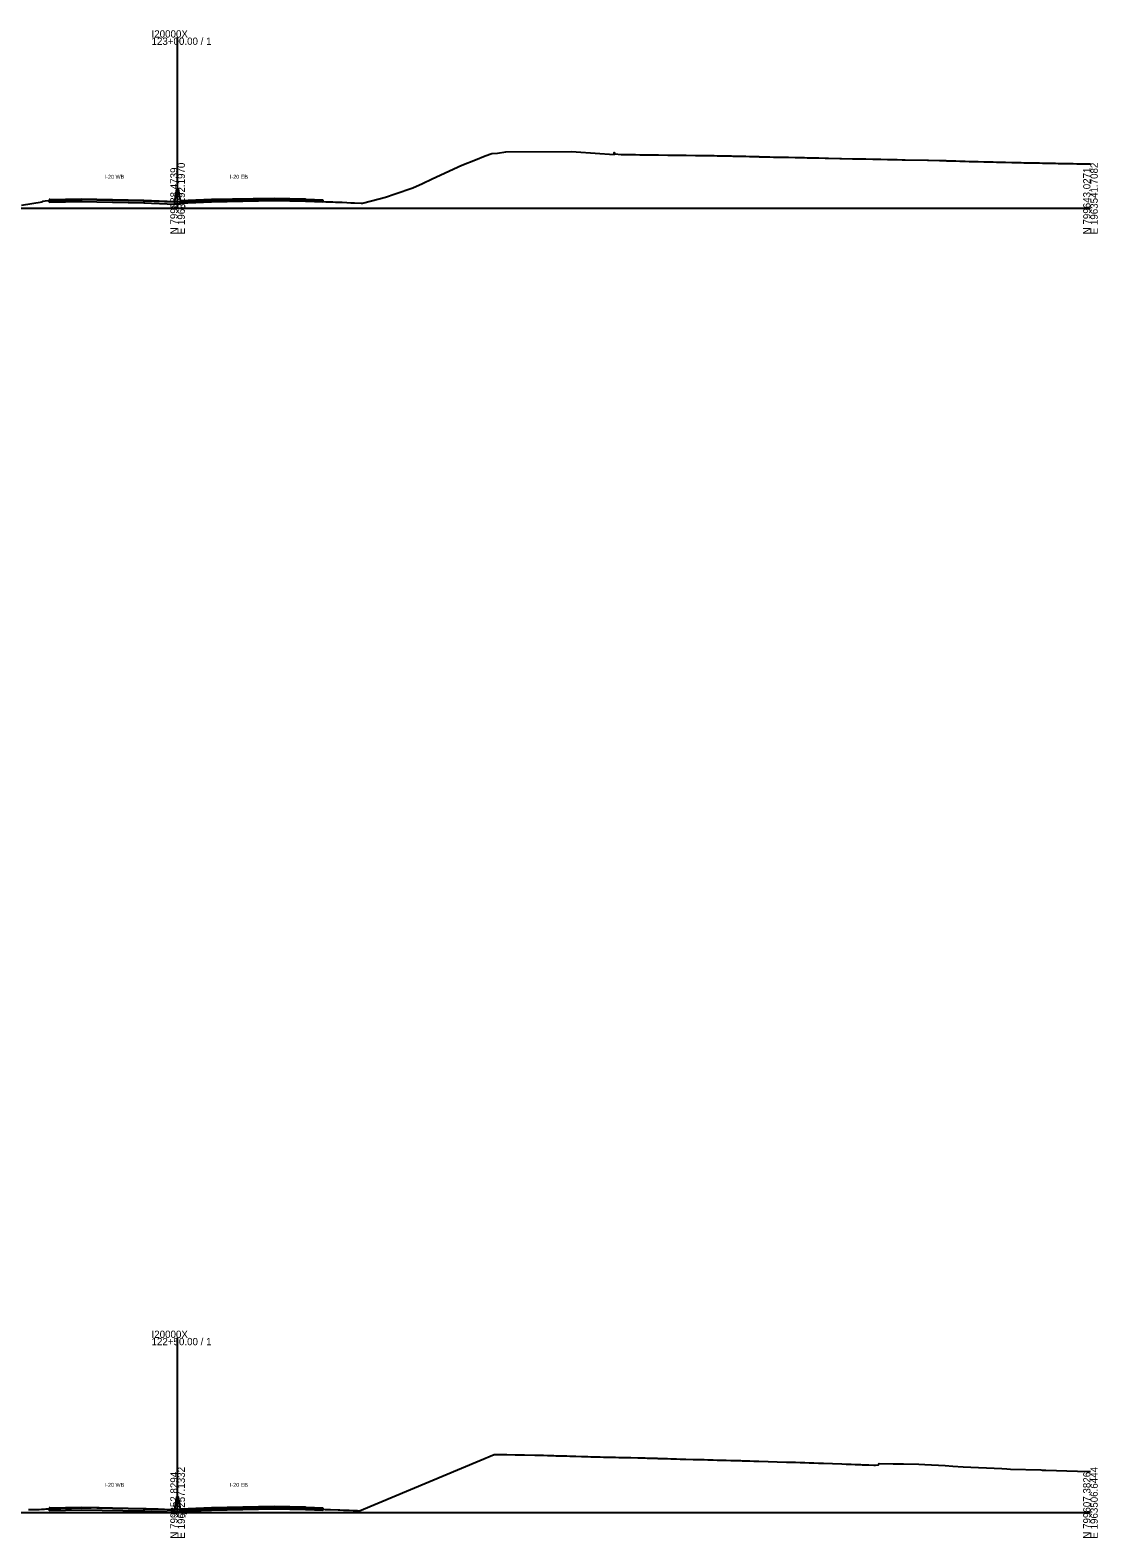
# Model space of a CAD drawing. Extents: x -4026 to 9638, y -10 to 19609.
# Drawn here: x 2293 to 2703, y 3990 to 4568 of the extents above; entities that cross this region are included whole.
import ezdxf

# ---------------------------------------------------------------- set-up
doc = ezdxf.new("R2010")
doc.units = 0
for name, color, linetype in [('RD_GPK_XS_Cell', 7, 'Continuous'), ('RD_TX_Misc1', 7, 'Continuous'), ('RD_XS_Base', 7, 'Continuous'), ('RD_XS_ExGround', 7, 'Continuous'), ('RD_XS_MedBWall', 7, 'Continuous'), ('RD_XS_Pave', 7, 'Continuous'), ('RD_XS_PaveOvlay', 7, 'Continuous'), ('RD_XS_TX_Elev_EX', 7, 'Continuous')]:
    doc.layers.add(name, color=color, linetype=linetype)

msp = doc.modelspace()

# ---------------------------------------------------------------- linework, layer by layer
at = {"layer": 'RD_GPK_XS_Cell'}
for p, q in [((2350, 4500), (2350, 4565.43)), ((2000, 4500), (2350, 4500)), ((2350, 4500), (2700, 4500)), ((2350, 4000), (2350, 4066.94)), ((2000, 4000), (2350, 4000)), ((2350, 4000), (2700, 4000))]:
    msp.add_line(p, q, dxfattribs=at)
at = {"layer": 'RD_XS_Base'}
for points in [[(2300.75, 4502.97), (2301, 4502.98)], [(2300.75, 4502.3), (2300.75, 4502.97)], [(2337, 4502.74), (2313, 4503.23), (2301, 4502.98)], [(2301, 4502.98), (2301, 4502.31)], [(2301, 4502.31), (2313, 4502.56), (2337, 4502.07)], [(2349, 4502.27), (2337, 4502.74)], [(2337, 4502.74), (2337, 4502.07)], [(2351, 4502.47), (2363, 4502.96)], [(2351, 4501.8), (2351, 4502.47)], [(2363, 4502.96), (2387, 4503.45), (2399, 4503.2)], [(2363, 4502.29), (2363, 4502.96)], [(2399, 4502.53), (2387, 4502.78), (2363, 4502.29)], [(2399, 4503.2), (2399.25, 4503.2)], [(2399, 4502.53), (2399, 4503.2)], [(2399.25, 4502.53), (2399, 4502.53)], [(2399.25, 4503.2), (2405.74, 4502.94)], [(2399.25, 4502.53), (2399.25, 4503.2)], [(2405.74, 4502.27), (2399.25, 4502.53)], [(2405.74, 4502.94), (2405.74, 4502.27)], [(2301, 4502.31), (2300.75, 4502.3)], [(2337, 4502.07), (2349, 4501.6)], [(2349, 4501.6), (2349, 4502.27)], [(2363, 4502.29), (2351, 4501.8)], [(2300.75, 4001.51), (2301, 4001.52)], [(2300.75, 4000.84), (2300.75, 4001.51)], [(2301, 4000.85), (2300.75, 4000.84)], [(2337, 4001.28), (2313, 4001.76), (2301, 4001.52)], [(2301, 4001.52), (2301, 4000.85)], [(2301, 4000.85), (2313, 4001.09), (2337, 4000.61)], [(2349, 4000.81), (2337, 4001.28)], [(2337, 4001.28), (2337, 4000.61)], [(2337, 4000.61), (2349, 4000.14)], [(2349, 4000.14), (2349, 4000.81)], [(2351, 4001.03), (2363, 4001.52)], [(2351, 4000.36), (2351, 4001.03)], [(2363, 4000.85), (2351, 4000.36)], [(2363, 4001.52), (2387, 4002.01), (2399, 4001.76)], [(2363, 4000.85), (2363, 4001.52)], [(2399, 4001.09), (2387, 4001.34), (2363, 4000.85)], [(2399, 4001.76), (2399.25, 4001.76)], [(2399, 4001.09), (2399, 4001.76)], [(2399.25, 4001.09), (2399, 4001.09)], [(2399.25, 4001.76), (2405.74, 4001.5)], [(2399.25, 4001.09), (2399.25, 4001.76)], [(2405.74, 4000.83), (2399.25, 4001.09)], [(2405.74, 4001.5), (2405.74, 4000.83)]]:
    msp.add_lwpolyline(points, dxfattribs=at)
at = {"layer": 'RD_XS_ExGround'}
for points in [[(2290.1, 4501.18), (2298.05, 4502.52), (2298.5, 4502.75), (2299.28, 4502.81), (2302.84, 4502.95), (2304.47, 4503), (2306.44, 4503.08), (2307.06, 4503.1), (2309.75, 4503.18), (2311.95, 4503.23), (2313.37, 4503.26), (2315.93, 4503.3), (2316.94, 4503.32), (2318.88, 4503.34), (2320.39, 4503.32), (2322.17, 4503.28), (2323.99, 4503.24), (2325.66, 4503.2), (2327.57, 4503.16), (2331.15, 4503.08), (2332.77, 4503.07), (2334.7, 4503.04), (2337.72, 4502.97), (2338.24, 4502.96), (2339.75, 4502.93), (2341.74, 4502.89), (2342.52, 4502.87), (2344.31, 4502.74), (2344.65, 4502.68), (2345.04, 4502.67), (2345.36, 4502.66), (2346.24, 4502.63), (2347.75, 4502.58), (2350, 4502.54), (2350.34, 4502.53), (2351.94, 4502.49), (2352.71, 4502.52), (2354.24, 4502.58), (2354.58, 4502.59), (2354.87, 4502.69), (2355.9, 4502.75), (2357.15, 4502.82), (2358.85, 4502.85), (2359.65, 4502.86), (2362.48, 4502.91), (2363.2, 4502.93), (2364.55, 4502.95), (2366.06, 4502.98), (2366.41, 4502.98), (2366.75, 4502.99), (2369.18, 4503.05), (2370.31, 4503.08), (2372.86, 4503.15), (2373.87, 4503.18), (2376.51, 4503.23), (2377.48, 4503.26), (2379.35, 4503.29), (2379.95, 4503.29), (2380.25, 4503.28), (2381.03, 4503.27), (2382.32, 4503.25), (2383.58, 4503.23), (2384.61, 4503.21), (2386.85, 4503.16), (2387.48, 4503.14), (2388.17, 4503.12), (2389.29, 4503.09), (2390.59, 4503.06), (2391.19, 4503.04), (2391.74, 4503.02), (2393.95, 4502.95), (2395.29, 4502.92), (2397.24, 4502.86), (2398.04, 4502.83), (2398.83, 4502.81), (2399.95, 4502.77), (2401.09, 4502.73), (2402.38, 4502.69), (2403.52, 4502.65), (2404.44, 4502.62), (2405.97, 4502.56), (2406.88, 4502.52), (2407.85, 4502.49), (2408.74, 4502.45), (2409.53, 4502.42), (2410.58, 4502.38), (2411.54, 4502.34), (2412.3, 4502.31), (2413.15, 4502.27), (2414.84, 4502.2), (2416.42, 4502.13), (2417.15, 4502.1), (2417.49, 4502.08), (2417.86, 4502.02), (2420.38, 4502), (2420.89, 4501.99), (2424.38, 4502.78), (2429.68, 4504.23), (2433.39, 4505.55), (2440.17, 4507.87), (2443.95, 4509.49), (2447.57, 4511.23), (2459.04, 4516.55), (2464.17, 4518.56), (2467.89, 4520.15), (2470.44, 4521), (2472.63, 4521.16), (2475.9, 4521.59), (2501.06, 4521.81), (2502.85, 4521.68), (2517.34, 4520.65), (2517.37, 4521.35), (2517.6, 4520.79), (2517.68, 4520.89), (2520.12, 4520.64), (2520.77, 4520.63), (2521.4, 4520.62), (2523.7, 4520.58), (2525.51, 4520.56), (2527.2, 4520.53), (2528.96, 4520.51), (2530.79, 4520.48), (2534.35, 4520.43), (2537.93, 4520.38), (2539.58, 4520.37), (2541.48, 4520.34), (2543.11, 4520.32), (2545.03, 4520.3), (2548.59, 4520.25), (2550.18, 4520.24), (2551.74, 4520.22), (2552.18, 4520.21), (2554.05, 4520.19), (2555.73, 4520.17), (2556.9, 4520.15), (2558.85, 4520.12), (2559.17, 4520.11), (2561.26, 4520.06), (2562.29, 4520.04), (2562.84, 4520.02), (2564.31, 4519.99), (2565.78, 4519.95), (2566.1, 4519.94), (2566.4, 4519.94), (2567.85, 4519.91), (2569.31, 4519.87), (2569.62, 4519.86), (2569.93, 4519.85), (2572.8, 4519.78), (2573.16, 4519.77), (2573.52, 4519.76), (2576.3, 4519.69), (2576.69, 4519.68), (2577.08, 4519.67), (2578.46, 4519.64), (2579.83, 4519.61), (2580.22, 4519.6), (2580.62, 4519.59), (2583.33, 4519.54), (2583.76, 4519.53), (2584.19, 4519.52), (2586.82, 4519.47), (2587.79, 4519.45), (2589.07, 4519.43), (2590.32, 4519.4), (2591.35, 4519.38), (2592.57, 4519.35), (2593.84, 4519.33), (2594.37, 4519.32), (2594.91, 4519.31), (2595.88, 4519.29), (2598.23, 4519.23), (2598.57, 4519.23), (2599.51, 4519.22), (2603.9, 4519.11), (2604.55, 4519.1), (2608.75, 4519), (2611.87, 4518.93), (2613.94, 4518.89), (2616.55, 4518.83), (2619.65, 4518.77), (2622.13, 4518.71), (2625.87, 4518.64), (2627.84, 4518.6), (2628.93, 4518.57), (2637.55, 4518.42), (2637.95, 4518.41), (2642.15, 4518.33), (2643.13, 4518.29), (2644.56, 4518.25), (2644.95, 4518.23), (2645.45, 4518.22), (2646.01, 4518.2), (2646.43, 4518.19), (2647.86, 4518.14), (2648.37, 4518.13), (2649.95, 4518.08), (2650.91, 4518.05), (2651.97, 4518.02), (2653.44, 4517.98), (2654.48, 4517.95), (2655.53, 4517.92), (2656.25, 4517.9), (2656.95, 4517.88), (2659.13, 4517.82), (2659.8, 4517.81), (2660.45, 4517.8), (2662.68, 4517.74), (2663.96, 4517.71), (2666.22, 4517.66), (2667.48, 4517.63), (2669.82, 4517.57), (2670.4, 4517.56), (2670.96, 4517.55), (2672.17, 4517.52), (2673.39, 4517.49), (2674.48, 4517.47), (2676.93, 4517.43), (2677.51, 4517.41), (2678.73, 4517.39), (2679.85, 4517.37), (2680.53, 4517.36), (2681.59, 4517.34), (2682.43, 4517.32), (2684.06, 4517.28), (2684.53, 4517.27), (2685, 4517.26), (2685.43, 4517.25), (2686.63, 4517.22), (2687.63, 4517.2), (2688.07, 4517.19), (2688.5, 4517.18), (2689.85, 4517.16), (2691.19, 4517.13), (2691.6, 4517.12), (2692.02, 4517.11), (2693.36, 4517.09), (2694.74, 4517.06), (2695.14, 4517.05), (2695.53, 4517.04), (2696.91, 4517.02), (2698.3, 4516.99), (2698.67, 4516.99), (2699.04, 4516.98), (2700, 4516.97)], [(2292.87, 4001.2), (2294.42, 4001.18), (2294.97, 4001.18), (2296.93, 4001.19), (2297.85, 4001.26), (2298.21, 4001.26), (2298.43, 4001.3), (2298.97, 4001.36), (2299.57, 4001.39), (2301.68, 4001.48), (2302.38, 4001.5), (2303.09, 4001.52), (2305.25, 4001.59), (2306.24, 4001.63), (2307.13, 4001.66), (2308.5, 4001.71), (2308.83, 4001.72), (2309.37, 4001.73), (2309.94, 4001.75), (2312.39, 4001.8), (2312.9, 4001.81), (2313.39, 4001.82), (2314.65, 4001.84), (2315.94, 4001.85), (2316.4, 4001.86), (2316.86, 4001.87), (2318.85, 4001.89), (2319.75, 4001.88), (2320.33, 4001.87), (2321.64, 4001.84), (2323.07, 4001.82), (2323.56, 4001.81), (2324.02, 4001.8), (2326.95, 4001.73), (2327.25, 4001.72), (2328.85, 4001.68), (2330.21, 4001.65), (2331.02, 4001.64), (2334.02, 4001.6), (2334.34, 4001.6), (2335.91, 4001.57), (2337.32, 4001.54), (2338.01, 4001.52), (2340.87, 4001.47), (2341.28, 4001.46), (2342.5, 4001.43), (2343.47, 4001.3), (2343.76, 4001.28), (2345.28, 4001.23), (2346.74, 4001.18), (2350, 4001.17), (2352.86, 4001.17), (2353.68, 4001.2), (2354.53, 4001.24), (2354.89, 4001.26), (2355.31, 4001.37), (2355.77, 4001.4), (2357.1, 4001.48), (2358.39, 4001.5), (2359.14, 4001.51), (2360.6, 4001.53), (2362.49, 4001.57), (2366.07, 4001.63), (2369.48, 4001.71), (2373.13, 4001.81), (2374.78, 4001.85), (2376.57, 4001.89), (2378.26, 4001.92), (2379.22, 4001.93), (2379.81, 4001.93), (2380.15, 4001.93), (2381.84, 4001.9), (2383.69, 4001.87), (2387.25, 4001.78), (2388.92, 4001.74), (2390.82, 4001.68), (2393.97, 4001.59), (2394.37, 4001.58), (2395.86, 4001.54), (2397.87, 4001.48), (2399.57, 4001.43), (2401.09, 4001.38), (2401.61, 4001.37), (2403.42, 4001.31), (2404.39, 4001.27), (2405.03, 4001.24), (2406.55, 4001.19), (2408.6, 4001.13), (2411.54, 4001.03), (2412.19, 4001.01), (2413.58, 4000.96), (2414.92, 4000.91), (2415.33, 4000.89), (2415.75, 4000.88), (2417.27, 4000.81), (2418.67, 4000.75), (2418.97, 4000.74), (2419.77, 4000.68), (2465.84, 4020.02), (2471.35, 4022.31), (2471.95, 4022.3), (2472.92, 4022.27), (2474.84, 4022.24), (2476.2, 4022.21), (2479.44, 4022.15), (2482.99, 4022.09), (2486.97, 4022.01), (2487.92, 4021.99), (2490.32, 4021.94), (2491.78, 4021.89), (2494.24, 4021.83), (2494.98, 4021.81), (2495.68, 4021.79), (2496.68, 4021.77), (2497.76, 4021.73), (2498.52, 4021.72), (2499.25, 4021.7), (2500.42, 4021.68), (2501.36, 4021.65), (2502.05, 4021.64), (2502.74, 4021.61), (2504.89, 4021.54), (2505.58, 4021.53), (2506.26, 4021.5), (2507.34, 4021.47), (2508.47, 4021.42), (2509.11, 4021.4), (2509.76, 4021.38), (2510.89, 4021.36), (2512.06, 4021.32), (2513.26, 4021.29), (2515.61, 4021.24), (2516.2, 4021.22), (2516.76, 4021.21), (2517.94, 4021.18), (2519.19, 4021.16), (2519.74, 4021.15), (2520.28, 4021.13), (2522.71, 4021.07), (2523.25, 4021.06), (2523.79, 4021.05), (2526.43, 4020.98), (2527.45, 4020.96), (2528.1, 4020.94), (2529.3, 4020.92), (2529.99, 4020.9), (2530.38, 4020.88), (2530.75, 4020.87), (2532.45, 4020.82), (2533.43, 4020.81), (2533.87, 4020.79), (2534.29, 4020.78), (2535.42, 4020.74), (2537, 4020.69), (2537.41, 4020.68), (2537.81, 4020.67), (2539.17, 4020.63), (2540.57, 4020.59), (2540.94, 4020.58), (2541.3, 4020.57), (2542.71, 4020.53), (2544.14, 4020.49), (2544.48, 4020.48), (2544.82, 4020.47), (2547.69, 4020.4), (2548.32, 4020.38), (2551.23, 4020.3), (2551.84, 4020.28), (2553.3, 4020.24), (2554.78, 4020.2), (2555.34, 4020.18), (2556.83, 4020.14), (2558.85, 4020.08), (2560.37, 4020.04), (2562.07, 4019.99), (2562.38, 4019.99), (2563.84, 4019.95), (2565.44, 4019.91), (2565.82, 4019.9), (2566.42, 4019.89), (2567.68, 4019.85), (2568.37, 4019.84), (2569.39, 4019.81), (2570.93, 4019.76), (2572.89, 4019.7), (2576.4, 4019.6), (2579.91, 4019.48), (2583.41, 4019.38), (2586.92, 4019.26), (2588.65, 4019.21), (2590.44, 4019.15), (2592.18, 4019.09), (2594, 4019.03), (2595.74, 4018.96), (2597.59, 4018.9), (2601.12, 4018.77), (2604.65, 4018.64), (2606.32, 4018.58), (2608.24, 4018.51), (2609.82, 4018.45), (2611.79, 4018.38), (2612.5, 4018.35), (2613.99, 4018.31), (2615.09, 4018.26), (2616.96, 4018.17), (2617.65, 4018.13), (2618.72, 4018.35), (2619.04, 4018.79), (2624.35, 4018.7), (2628.38, 4018.64), (2634.14, 4018.61), (2636.5, 4018.48), (2644.24, 4018.02), (2647.26, 4017.83), (2651.15, 4017.58), (2666.08, 4016.84), (2667.92, 4016.75), (2669.3, 4016.69), (2681, 4016.32), (2681.48, 4016.3), (2682.22, 4016.28), (2682.93, 4016.25), (2695.09, 4015.91), (2700, 4015.72)]]:
    msp.add_lwpolyline(points, dxfattribs=at)
at = {"layer": 'RD_XS_MedBWall'}
for points in [[(2349, 4502.6), (2349.75, 4507.47), (2350.25, 4507.47), (2351, 4502.8)], [(2349, 4501.6), (2349, 4502.6)], [(2351, 4502.8), (2351, 4501.6)], [(2351, 4501.6), (2349, 4501.6)], [(2349, 4001.14), (2349.75, 4006.03), (2350.25, 4006.03), (2351, 4001.36)], [(2349, 4000.14), (2349, 4001.14)], [(2351, 4000.14), (2349, 4000.14)], [(2351, 4001.36), (2351, 4000.14)]]:
    msp.add_lwpolyline(points, dxfattribs=at)
at = {"layer": 'RD_XS_Pave'}
for points in [[(2300.75, 4503.14), (2301, 4503.15)], [(2300.75, 4502.97), (2300.75, 4503.14)], [(2301, 4502.98), (2300.75, 4502.97)], [(2301, 4503.15), (2313, 4503.39), (2337, 4502.91)], [(2337, 4502.74), (2313, 4503.23), (2301, 4502.98)], [(2301, 4503.15), (2301, 4502.98)], [(2337, 4502.91), (2337, 4502.74)], [(2337, 4502.91), (2349, 4502.44)], [(2349, 4502.27), (2337, 4502.74)], [(2349, 4502.44), (2349, 4502.27)], [(2363, 4503.13), (2351, 4502.64)], [(2351, 4502.47), (2363, 4502.96)], [(2351, 4502.64), (2351, 4502.47)], [(2399, 4503.37), (2387, 4503.61), (2363, 4503.13)], [(2363, 4502.96), (2387, 4503.45), (2399, 4503.2)], [(2363, 4503.13), (2363, 4502.96)], [(2399, 4503.37), (2399.25, 4503.37)], [(2399, 4503.2), (2399, 4503.37)], [(2399.25, 4503.2), (2399, 4503.2)], [(2399.25, 4503.37), (2399.25, 4503.2)], [(2399.25, 4503.37), (2405.74, 4503.11)], [(2405.74, 4502.94), (2399.25, 4503.2)], [(2405.74, 4503.11), (2405.74, 4502.94)], [(2300.75, 4001.68), (2301, 4001.69)], [(2300.75, 4001.51), (2300.75, 4001.68)], [(2301, 4001.52), (2300.75, 4001.51)], [(2301, 4001.69), (2313, 4001.93), (2337, 4001.45)], [(2337, 4001.28), (2313, 4001.76), (2301, 4001.52)], [(2301, 4001.69), (2301, 4001.52)], [(2337, 4001.45), (2337, 4001.28)], [(2337, 4001.45), (2349, 4000.98)], [(2349, 4000.81), (2337, 4001.28)], [(2349, 4000.98), (2349, 4000.81)], [(2363, 4001.69), (2351, 4001.2)], [(2351, 4001.03), (2363, 4001.52)], [(2351, 4001.2), (2351, 4001.03)], [(2399, 4001.93), (2387, 4002.17), (2363, 4001.69)], [(2363, 4001.52), (2387, 4002.01), (2399, 4001.76)], [(2363, 4001.69), (2363, 4001.52)], [(2399, 4001.93), (2399.25, 4001.93)], [(2399, 4001.76), (2399, 4001.93)], [(2399.25, 4001.76), (2399, 4001.76)], [(2399.25, 4001.93), (2399.25, 4001.76)], [(2399.25, 4001.93), (2405.74, 4001.67)], [(2405.74, 4001.5), (2399.25, 4001.76)], [(2405.74, 4001.67), (2405.74, 4001.5)]]:
    msp.add_lwpolyline(points, dxfattribs=at)
at = {"layer": 'RD_XS_PaveOvlay'}
for points in [[(2301, 4503.32), (2300.75, 4503.31)], [(2300.75, 4503.31), (2300.75, 4503.14)], [(2300.75, 4503.14), (2301, 4503.15)], [(2301, 4503.32), (2313, 4503.56), (2337, 4503.08)], [(2337, 4502.91), (2313, 4503.39), (2301, 4503.15)], [(2301, 4503.15), (2301, 4503.32)], [(2337, 4503.08), (2337, 4502.91)], [(2337, 4503.08), (2349, 4502.6)], [(2349, 4502.44), (2337, 4502.91)], [(2349, 4502.6), (2349, 4502.44)], [(2363, 4503.3), (2351, 4502.8)], [(2351, 4502.64), (2363, 4503.13)], [(2351, 4502.8), (2351, 4502.64)], [(2399, 4503.54), (2387, 4503.78), (2363, 4503.3)], [(2363, 4503.13), (2387, 4503.61), (2399, 4503.37)], [(2363, 4503.3), (2363, 4503.13)], [(2399, 4503.37), (2399, 4503.54)], [(2399, 4503.54), (2399.25, 4503.54)], [(2399.25, 4503.37), (2399, 4503.37)], [(2399.25, 4503.54), (2405.74, 4503.28)], [(2399.25, 4503.37), (2399.25, 4503.54)], [(2405.74, 4503.11), (2399.25, 4503.37)], [(2405.74, 4503.28), (2405.74, 4503.11)], [(2301, 4001.86), (2300.75, 4001.85)], [(2300.75, 4001.85), (2300.75, 4001.68)], [(2300.75, 4001.68), (2301, 4001.69)], [(2301, 4001.86), (2313, 4002.1), (2337, 4001.62)], [(2337, 4001.45), (2313, 4001.93), (2301, 4001.69)], [(2301, 4001.69), (2301, 4001.86)], [(2337, 4001.62), (2337, 4001.45)], [(2337, 4001.62), (2349, 4001.14)], [(2349, 4000.98), (2337, 4001.45)], [(2349, 4001.14), (2349, 4000.98)], [(2363, 4001.86), (2351, 4001.36)], [(2351, 4001.2), (2363, 4001.69)], [(2351, 4001.36), (2351, 4001.2)], [(2399, 4002.1), (2387, 4002.34), (2363, 4001.86)], [(2363, 4001.69), (2387, 4002.17), (2399, 4001.93)], [(2363, 4001.86), (2363, 4001.69)], [(2399, 4001.93), (2399, 4002.1)], [(2399, 4002.1), (2399.25, 4002.1)], [(2399.25, 4001.93), (2399, 4001.93)], [(2399.25, 4002.1), (2405.74, 4001.84)], [(2399.25, 4001.93), (2399.25, 4002.1)], [(2405.74, 4001.67), (2399.25, 4001.93)], [(2405.74, 4001.84), (2405.74, 4001.67)]]:
    msp.add_lwpolyline(points, dxfattribs=at)

# ---------------------------------------------------------------- texts
at = {"layer": 'RD_GPK_XS_Cell'}
for s, p in [('I20000X', (2340, 4565.43)), ('123+00.00 / 1', (2340, 4562.63)), ('I20000X', (2340, 4066.94)), ('122+50.00 / 1', (2340, 4064.14))]:
    msp.add_text(s, height=2.8, dxfattribs=at).set_placement(p)
for s, p in [('N 799888.4739', (2350, 4490)), ('E 1963292.1970', (2352.8, 4490)), ('N 799643.0271', (2700, 4490)), ('E 1963541.7082', (2702.8, 4490)), ('E 1963257.1332', (2352.8, 3990)), ('E 1963506.6444', (2702.8, 3990)), ('N 799852.8294', (2350, 3990)), ('N 799607.3826', (2700, 3990))]:
    msp.add_text(s, height=2.8, rotation=90, dxfattribs=at).set_placement(p)
at = {"layer": 'RD_TX_Misc1'}
for s, p in [('I-20 WB', (2322.06, 4511.31)), ('I-20 EB', (2370.06, 4511.31)), ('I-20 WB', (2322.06, 4009.88)), ('I-20 EB', (2370.06, 4009.88))]:
    msp.add_text(s, height=1.5, dxfattribs=at).set_placement(p)
at = {"layer": 'RD_XS_TX_Elev_EX'}
for s, p in [('227.54', (2347.05, 4499.54)), ('226.17', (2347.32, 3998.17))]:
    msp.add_text(s, height=1.5, dxfattribs=at).set_placement(p)

doc.saveas('drawing.dxf')
